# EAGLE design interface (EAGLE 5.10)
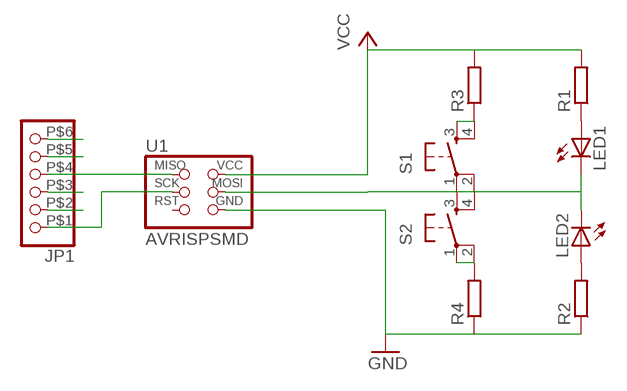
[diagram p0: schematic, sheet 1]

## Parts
JP1  PINHD-1X6SMD  [1X06SMD]
LED1  LEDCHIPLED_1206  [CHIPLED_1206]
LED2  LEDCHIPLED_1206  [CHIPLED_1206]
R1  R-EU_R1206  [R1206]
R2  R-EU_R1206  [R1206]
R3  R-EU_R1206  [R1206]
R4  R-EU_R1206  [R1206]
S1  6MM_SWITCH6MM_SWITCH  [6MM_SWITCH]
S2  6MM_SWITCH6MM_SWITCH  [6MM_SWITCH]
U1  AVRISPSMD  [2X03SMD]

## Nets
GND: JP1.P$2 JP1.P$5 R2.1 R4.1 U1.6(GND)
N$1: LED1.A R1.1
N$2: LED2.A R2.2
N$3: R3.1 S1.3(S) S1.4(S1)
N$4: R4.2 S2.1(P) S2.2(P1)
N$7: LED1.C LED2.C S1.1(P) S1.2(P1) S2.3(S) S2.4(S1) U1.4(MOSI)
N$12: JP1.P$4 U1.1(MISO)
N$13: JP1.P$1 U1.3(SCK)
VCC: JP1.P$3 JP1.P$6 R1.2 R3.2 U1.2(VCC)
Unconnected: U1.5(RST)

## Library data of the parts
JP1 = fab-lib:PINHD-1X6: PIN HEADER
LED1 LED2 = led:LED: LED
R1-R4 = rcl:R-EU_: RESISTOR, European symbol
S1 S2 = fab:6MM_SWITCH: OMRON SWITCH
U1 = fab:AVRISP

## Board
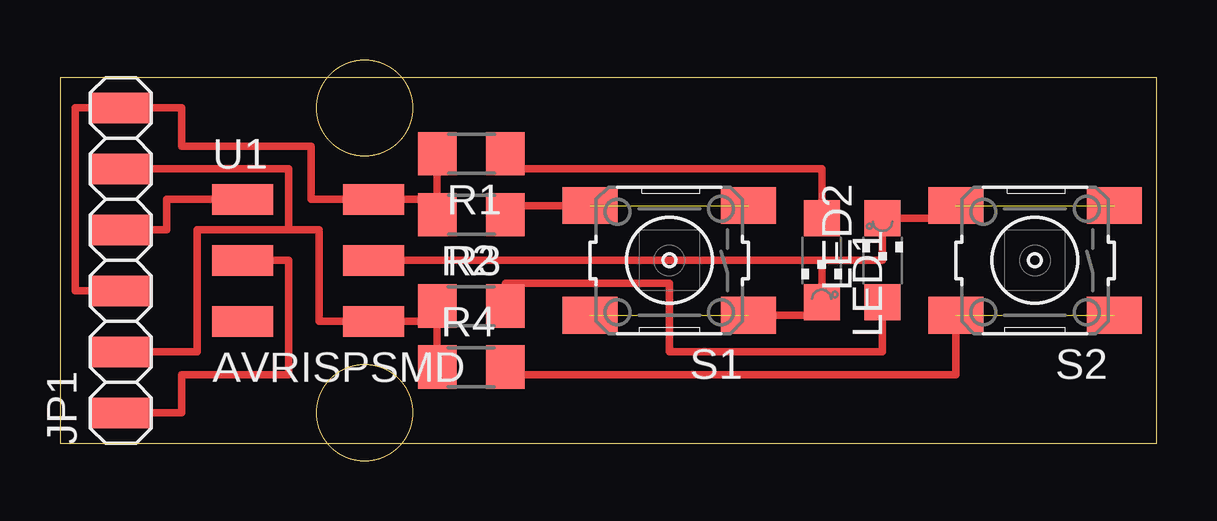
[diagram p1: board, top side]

Size 45.72 x 16.7 mm. Coordinates in mm from the lower left corner, seen from the top.
Outline: 0,0.73 45.72,0.73 45.72,15.97 0,15.97 0,0.73
Outline: circle at 12.7,14.7 radius 2
Outline: circle at 12.7,2 radius 2
Copper layers (1*16): Top 0.035mm / dielectric 1.5mm / Bottom 0.035mm
Design rules "fab-.25mm *": minimum track width 10mil, minimum drill 24mil, track to track 15mil, track to pad 15mil, pad to pad 15mil, via to via 15mil, smd to smd 8mil, copper to edge 1mil, drill to drill 8mil, minimum pad ring 10mil, minimum via ring 8mil, stop-mask expansion 4mil, vias tented up to drill 0mil, thermal gap 10mil

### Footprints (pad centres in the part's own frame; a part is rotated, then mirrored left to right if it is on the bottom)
1X06SMD = smd 1.27 x 2.54: P$1 -6.35,0; P$2 -3.81,0; P$3 -1.27,0; P$4 1.27,0; P$5 3.81,0; P$6 6.35,0
CHIPLED_1206 = smd 1.5 x 1.5: A 0,-1.75; C 0,1.75
R1206 = smd 1.6 x 1.803: 1 -1.422,0; 2 1.422,0
6MM_SWITCH = smd 2.286 x 1.524: 1 -3.302,2.286; 2 3.302,2.286; 3 -3.302,-2.286; 4 3.302,-2.286
2X03SMD = smd 2.54 x 1.27: 1 -2.54,2.54; 2 2.92,2.54; 3 -2.54,0; 4 2.92,0; 5 -2.54,-2.54; 6 2.92,-2.54

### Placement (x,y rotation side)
JP1  2.54,8.35 90 top
LED1  31.75,8.35 180 top
LED2  34.29,8.35 0 top
R1  17.14,12.79 180 top
R2  17.14,6.45 0 top
R3  17.14,10.26 180 top
R4  17.14,3.9 0 top
S1  25.4,8.35 180 top
S2  40.64,8.35 180 top
U1  10.16,8.35 0 top

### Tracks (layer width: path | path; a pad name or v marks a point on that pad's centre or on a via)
GND
  Top 0.305: JP1.P$5 9.53,12.16 9.53,9.62 | 9.53,9.62 5.71,9.62 5.71,4.54 JP1.P$2 | 9.53,9.62 10.79,9.62 10.79,5.81 U1.6 15.72,5.81 R2.1 R4.1
N$1
  Top 0.305: R1.1 18.57,12.16 30.48,12.16 31.75,12.16 LED1.A
N$2
  Top 0.305: R2.2 18.57,7.4 25.4,7.4 25.4,4.54 34.29,4.54 LED2.A
N$3  (1 unrouted)
  Top 0.305: R3.1 18.57,10.64 S1.4
N$4  (1 unrouted)
  Top 0.305: S2.2 37.34,3.59 18.57,3.59 R4.2
N$7  (2 unrouted)
  Top 0.305: S2.4 37.34,10.1 LED2.C 34.29,8.35 31.75,8.35 | U1.4 31.75,8.35 | 31.75,8.35 LED1.C 31.75,6.06 S1.1
N$12
  Top 0.305: U1.1 4.45,10.89 4.45,9.62 JP1.P$4
N$13
  Top 0.305: U1.3 9.53,8.35 9.53,3.59 5.08,3.59 5.08,2 JP1.P$1
VCC
  Top 0.305: JP1.P$3 0.64,7.08 0.64,14.7 JP1.P$6 5.08,14.7 5.08,13.11 10.48,13.11 10.48,10.89 U1.2 15.72,10.89 | 15.72,10.89 R3.2 | 15.72,10.89 R1.2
